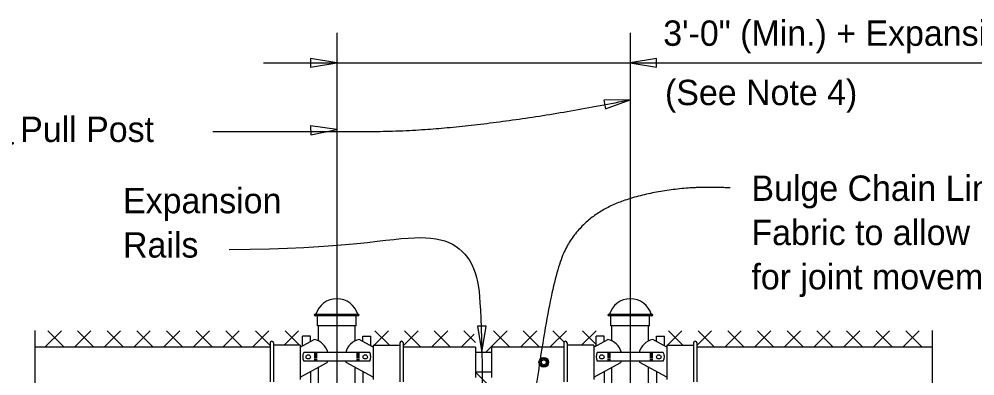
# Model space of a CAD drawing. Extents: x 0.4 to 38.5, y 1.2 to 25.4.
# Drawn here: x 23.59 to 31.18, y 22.6 to 25.44 of the extents above; entities that cross this region are included whole.
import ezdxf

# ---------------------------------------------------------------- set-up
doc = ezdxf.new("R2010")
doc.units = 0
for name, color, linetype in [('CL_Major', 7, 'Continuous'), ('Dimension', 7, 'Continuous'), ('Miscellaneous', 7, 'Continuous'), ('SteelMisc', 7, 'Continuous'), ('TextStructures', 7, 'Continuous')]:
    doc.layers.add(name, color=color, linetype=linetype)

msp = doc.modelspace()

# ---------------------------------------------------------------- linework, layer by layer
at = {"layer": 'CL_Major'}
for p, q in [((26.1118, 25.3255), (26.1118, 12.6331)), ((28.4451, 25.3255), (28.4451, 13.7657))]:
    msp.add_line(p, q, dxfattribs=at)
at = {"layer": 'Dimension'}
msp.add_line((25.5298, 25.0883), (34.4327, 25.0883), dxfattribs=at)
for points in [[(26.1118, 25.0883), (25.9036, 25.1236), (25.9036, 25.053)], [(28.4452, 25.0883), (28.6534, 25.053), (28.6534, 25.1236)], [(28.4452, 24.7949), (28.234, 24.7914), (28.2469, 24.722)], [(26.1118, 24.5582), (25.9026, 24.5871), (25.9047, 24.5166)], [(27.2647, 22.7854), (27.3, 22.9937), (27.2295, 22.9937)]]:
    msp.add_lwpolyline(points, close=True, dxfattribs=at)
for points in [[(23.712, 22.9593), (23.712, 21.0031), (23.8154, 21.0031), (23.712, 20.9581), (23.6087, 20.9131), (23.712, 20.9131), (23.712, 20.0194)], [(30.8451, 22.9593), (30.8451, 21.0031), (30.9484, 21.0031), (30.8451, 20.9581), (30.7418, 20.9131), (30.8451, 20.9131), (30.8451, 20.0194)]]:
    msp.add_lwpolyline(points, dxfattribs=at)
for points, degree in [([(25.1277, 24.5426), (25.5814, 24.5426), (27.1777, 24.5426), (28.4451, 24.7949)], 2), ([(29.2401, 24.0936), (28.8116, 24.1189), (28.0806, 23.9002), (27.7781, 23.3115), (27.6101, 21.8045)], 2), ([(25.2573, 23.6051), (26.1819, 23.6051), (26.8868, 23.7931), (27.2773, 23.5118), (27.2785, 22.9517), (27.2785, 17.3687)], 3)]:
    msp.add_open_spline(points, degree=degree, dxfattribs=at)
at = {"layer": 'Miscellaneous'}
for p, q in [((23.9227, 22.9573), (23.7925, 22.8271)), ((23.9454, 22.8271), (23.8152, 22.9573)), ((24.1584, 22.9573), (24.0282, 22.8271)), ((24.1811, 22.8271), (24.0509, 22.9573)), ((24.3941, 22.9573), (24.2639, 22.8271)), ((24.4168, 22.8271), (24.2866, 22.9573)), ((24.6298, 22.9573), (24.4996, 22.8271)), ((24.6525, 22.8271), (24.5223, 22.9573)), ((24.8655, 22.9573), (24.7353, 22.8271)), ((24.8882, 22.8271), (24.758, 22.9573)), ((25.1012, 22.9573), (24.971, 22.8271)), ((25.1239, 22.8271), (24.9937, 22.9573)), ((25.3369, 22.9573), (25.2067, 22.8271)), ((25.3596, 22.8271), (25.2294, 22.9573)), ((25.5726, 22.9573), (25.4424, 22.8271)), ((25.5825, 22.8399), (25.4651, 22.9573)), ((25.8083, 22.9573), (25.6935, 22.8425)), ((25.8156, 22.8425), (25.7008, 22.9573)), ((26.4081, 22.8425), (26.5228, 22.9573)), ((26.4154, 22.9573), (26.5301, 22.8425)), ((26.6412, 22.8399), (26.7585, 22.9573)), ((26.6511, 22.9573), (26.7812, 22.8271)), ((26.864, 22.8271), (26.9942, 22.9573)), ((26.8868, 22.9573), (27.0169, 22.8271)), ((27.1225, 22.9573), (27.2146, 22.8651)), ((27.2938, 22.7854), (27.4656, 22.9573)), ((27.3582, 22.9573), (27.4883, 22.8271)), ((27.5712, 22.8271), (27.7013, 22.9573)), ((27.5939, 22.9573), (27.724, 22.8271)), ((27.8069, 22.8271), (27.937, 22.9573)), ((27.8296, 22.9573), (27.9158, 22.8711)), ((28.058, 22.8425), (28.1727, 22.9573)), ((28.0653, 22.9573), (28.1743, 22.8483)), ((28.7414, 22.8425), (28.8561, 22.9573)), ((28.7487, 22.9573), (28.8634, 22.8425)), ((28.9745, 22.8399), (29.0918, 22.9573)), ((28.9844, 22.9573), (29.1146, 22.8271)), ((29.1974, 22.8271), (29.3275, 22.9573)), ((29.2201, 22.9573), (29.3503, 22.8271)), ((29.4331, 22.8271), (29.5632, 22.9573)), ((29.4558, 22.9573), (29.586, 22.8271)), ((29.6688, 22.8271), (29.7989, 22.9573)), ((29.6915, 22.9573), (29.8217, 22.8271)), ((29.9045, 22.8271), (30.0347, 22.9573)), ((29.9272, 22.9573), (30.0574, 22.8271)), ((30.1402, 22.8271), (30.2704, 22.9573)), ((30.1629, 22.9573), (30.2931, 22.8271)), ((30.3759, 22.8271), (30.5061, 22.9573)), ((30.3986, 22.9573), (30.5288, 22.8271)), ((30.6116, 22.8271), (30.7418, 22.9573)), ((30.6343, 22.9573), (30.7645, 22.8271)), ((27.0997, 22.8271), (27.2045, 22.9319)), ((27.2149, 22.6292), (28.1743, 21.6697))]:
    msp.add_line(p, q, dxfattribs=at)
at = {"layer": 'SteelMisc'}
for p, q in [((25.9395, 23.0892), (26.2841, 23.0892)), ((26.2841, 23.077), (25.9395, 23.077)), ((25.9578, 22.9972), (25.9578, 23.077)), ((26.2659, 22.9972), (26.2659, 23.077)), ((28.2729, 23.0892), (28.6174, 23.0892)), ((28.6174, 23.077), (28.2729, 23.077)), ((28.2911, 22.9972), (28.2911, 23.077)), ((28.5992, 22.9972), (28.5992, 23.077)), ((26.2659, 22.9972), (25.9578, 22.9972)), ((25.966, 22.8773), (25.966, 22.9972)), ((26.2577, 22.8773), (26.2577, 22.9972)), ((28.5992, 22.9972), (28.2911, 22.9972)), ((28.2994, 22.8773), (28.2994, 22.9972)), ((28.591, 22.8773), (28.591, 22.9972)), ((25.8222, 22.8278), (25.9331, 22.8892)), ((25.8409, 22.8381), (25.8409, 22.9156)), ((25.9034, 22.9156), (25.8409, 22.9156)), ((25.9034, 22.8727), (25.9034, 22.9156)), ((26.4014, 22.8278), (26.2905, 22.8892)), ((26.3202, 22.8739), (26.3202, 22.9156)), ((26.3202, 22.9156), (26.3827, 22.9156)), ((26.3827, 22.8381), (26.3827, 22.9156)), ((28.1556, 22.8278), (28.2664, 22.8892)), ((28.1743, 22.8381), (28.1743, 22.9156)), ((28.2368, 22.9156), (28.1743, 22.9156)), ((28.2368, 22.8727), (28.2368, 22.9156)), ((28.7347, 22.8278), (28.6239, 22.8892)), ((28.6535, 22.8739), (28.6535, 22.9156)), ((28.6535, 22.9156), (28.716, 22.9156)), ((28.716, 22.8381), (28.716, 22.9156)), ((25.5825, 22.8271), (23.712, 22.8271)), ((25.5824, 22.8621), (25.5824, 22.5524)), ((25.6093, 22.8621), (25.6093, 22.5524)), ((25.8222, 22.8425), (25.6093, 22.8425)), ((25.8222, 22.8425), (25.8222, 22.5703)), ((26.4014, 22.8425), (26.4014, 22.5703)), ((26.4014, 22.8425), (26.6143, 22.8425)), ((26.6143, 22.8621), (26.6143, 22.5524)), ((26.6411, 22.8621), (26.6411, 22.5524)), ((27.216, 22.8271), (26.6412, 22.8271)), ((27.216, 22.8271), (27.216, 22.5875)), ((27.341, 22.8271), (27.341, 22.5875)), ((27.9158, 22.8271), (27.341, 22.8271)), ((27.9158, 22.8621), (27.9158, 22.5524)), ((27.9426, 22.8621), (27.9426, 22.5524)), ((28.1556, 22.8425), (27.9426, 22.8425)), ((28.1556, 22.8425), (28.1556, 22.5703)), ((28.7347, 22.8425), (28.7347, 22.5703)), ((28.7347, 22.8425), (28.9477, 22.8425)), ((28.9477, 22.8621), (28.9477, 22.5524)), ((28.9745, 22.8621), (28.9745, 22.5524)), ((30.845, 22.8271), (28.9745, 22.8271)), ((26.3742, 22.7852), (25.8494, 22.7852)), ((26.3742, 22.7174), (25.8494, 22.7174)), ((25.9318, 22.7774), (25.9553, 22.7774)), ((25.9318, 22.7678), (25.9553, 22.7678)), ((25.9318, 22.757), (25.9553, 22.757)), ((25.9318, 22.7452), (25.9553, 22.7452)), ((25.9318, 22.7334), (25.9553, 22.7334)), ((25.9318, 22.7236), (25.9553, 22.7236)), ((26.2918, 22.7774), (26.2683, 22.7774)), ((26.2918, 22.7678), (26.2683, 22.7678)), ((26.2918, 22.757), (26.2683, 22.757)), ((26.2918, 22.7452), (26.2683, 22.7452)), ((26.2918, 22.7334), (26.2683, 22.7334)), ((26.2918, 22.7236), (26.2683, 22.7236)), ((27.341, 22.7854), (27.216, 22.7854)), ((28.7075, 22.7852), (28.1827, 22.7852)), ((28.7075, 22.7174), (28.1827, 22.7174)), ((28.2651, 22.7774), (28.2886, 22.7774)), ((28.2651, 22.7678), (28.2886, 22.7678)), ((28.2651, 22.757), (28.2886, 22.757)), ((28.2651, 22.7452), (28.2886, 22.7452)), ((28.2651, 22.7334), (28.2886, 22.7334)), ((28.2651, 22.7236), (28.2886, 22.7236)), ((28.6252, 22.7774), (28.6017, 22.7774)), ((28.6252, 22.7678), (28.6017, 22.7678)), ((28.6252, 22.757), (28.6017, 22.757)), ((28.6252, 22.7452), (28.6017, 22.7452)), ((28.6252, 22.7334), (28.6017, 22.7334)), ((28.6252, 22.7236), (28.6017, 22.7236)), ((25.8222, 22.5884), (26.0362, 22.707)), ((25.966, 22.5083), (25.966, 22.6681)), ((26.4014, 22.5884), (26.1874, 22.707)), ((26.2577, 22.5083), (26.2577, 22.668)), ((28.1556, 22.5884), (28.3695, 22.707)), ((28.2994, 22.5083), (28.2994, 22.6681)), ((28.7347, 22.5884), (28.5207, 22.707)), ((28.591, 22.5083), (28.591, 22.668)), ((25.9034, 22.6334), (25.9034, 22.5083)), ((26.3202, 22.6334), (26.3202, 22.4407)), ((26.3202, 22.6334), (26.3202, 22.5865)), ((27.341, 22.6292), (27.216, 22.6292)), ((28.2368, 22.6334), (28.2368, 22.5083)), ((28.6535, 22.6334), (28.6535, 22.4407)), ((28.6535, 22.6334), (28.6535, 22.5865))]:
    msp.add_line(p, q, dxfattribs=at)
msp.add_lwpolyline([(27.7411, 22.736), (27.7742, 22.736), (27.7908, 22.7073), (27.7742, 22.6786), (27.7411, 22.6786), (27.7245, 22.7073)], close=True, dxfattribs=at)
for radius in [0.0382, 0.0191]:
    msp.add_circle((27.7577, 22.7073), radius, dxfattribs=at)
for centre, radius, start, end in [((25.9397, 23.0829), 0.00613, 91.1647, 268.8353), ((26.284, 23.0829), 0.00613, 271.1647, 88.8353), ((28.273, 23.0829), 0.00613, 91.1647, 268.8353), ((28.6173, 23.0829), 0.00613, 271.1647, 88.8353), ((25.596, 22.862), 0.0134, 0, 180), ((26.6277, 22.862), 0.0134, 0, 180), ((27.9293, 22.862), 0.0134, 0, 180), ((28.961, 22.862), 0.0134, 0, 180)]:
    msp.add_arc(centre, radius, start, end, dxfattribs=at)
for centre, major_axis, start_param, end_param in [((26.1125, 23.0482), (0.1711, 0), 0.252602, 2.888574), ((28.4458, 23.0482), (0.1711, 0), 0.252602, 2.888574), ((25.8986, 22.7532), (0.146, 0), 0.231126, 1.331255), ((26.325, 22.7532), (-0.146, 0), 4.95193, 6.05206), ((28.2319, 22.7532), (0.146, 0), 0.231126, 1.331255), ((28.6584, 22.7532), (-0.146, 0), 4.95193, 6.05206), ((25.9186, 22.7512), (-0.0776, 0), 5.810211, 6.75616), ((25.8986, 22.7532), (0.146, 0), 5.947976, 6.024627), ((26.325, 22.7532), (-0.146, 0), 0.258558, 0.335209), ((26.3051, 22.7512), (0.0776, 0), 5.810211, 6.75616), ((28.2519, 22.7512), (-0.0776, 0), 5.810211, 6.75616), ((28.2319, 22.7532), (0.146, 0), 5.947976, 6.024627), ((28.6584, 22.7532), (-0.146, 0), 0.258558, 0.335209), ((28.6384, 22.7512), (0.0776, 0), 5.810211, 6.75616)]:
    msp.add_ellipse(centre, major_axis=major_axis, ratio=0.957868, start_param=start_param, end_param=end_param, dxfattribs=at)
for centre, major_axis in [((25.8853, 22.7508), (0.0178, 0)), ((26.3384, 22.7508), (-0.0178, 0)), ((28.2186, 22.7508), (0.0178, 0)), ((28.6717, 22.7508), (-0.0178, 0))]:
    msp.add_ellipse(centre, major_axis=major_axis, ratio=0.957868, dxfattribs=at)

# ---------------------------------------------------------------- texts
at = {"layer": 'Dimension'}
for s, p in [('Bulge Chain Link ', (29.4081, 23.9909)), ('Expansion', (24.4131, 23.8921)), ('Fabric to allow ', (29.4081, 23.6389)), ('Rails', (24.4131, 23.5401)), ('for joint movement', (29.4081, 23.2869))]:
    msp.add_text(s, height=0.2016, dxfattribs=at).set_placement(p)
at = {"layer": 'TextStructures'}
for s, p in [('3\'-0" (Min.) + Expansion Joint Opening', (28.7069, 25.2234)), ('(See Note 4)', (28.7212, 24.7517)), ('℄ Pull Post', (23.4113, 24.4589))]:
    msp.add_text(s, height=0.2016, dxfattribs=at).set_placement(p)

doc.saveas('drawing.dxf')
